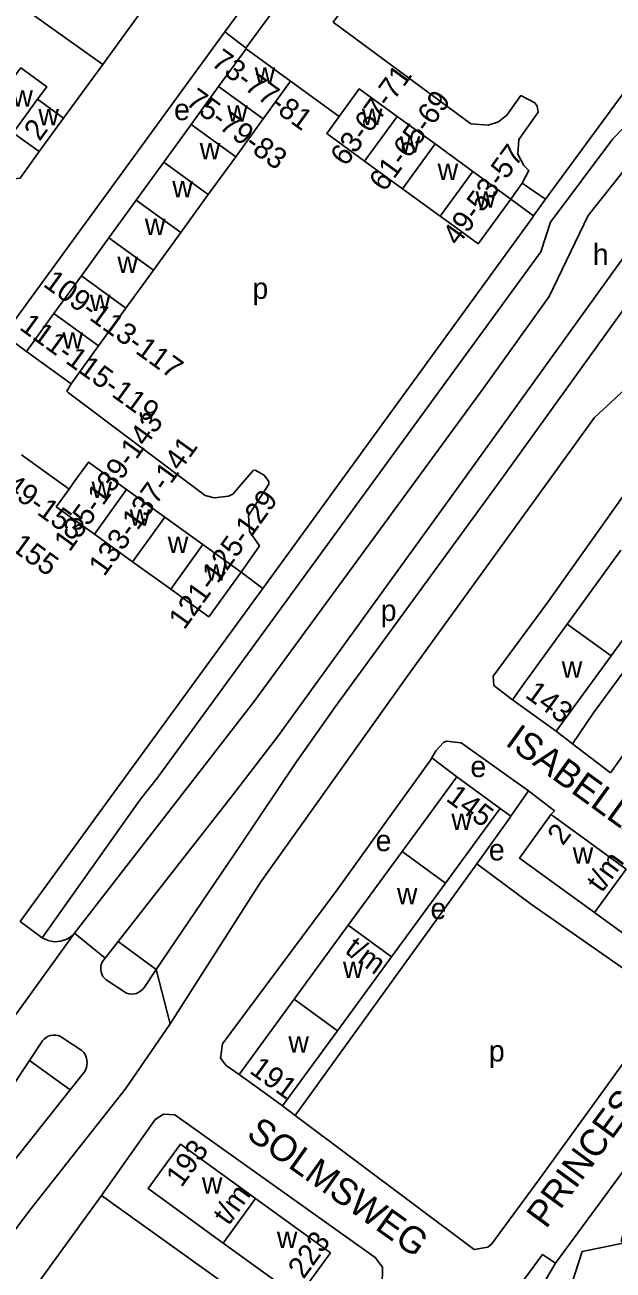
# Model space of a CAD drawing. Extents: x 159700 to 161346, y 381730 to 382922.
# Drawn here: x 160249.2 to 160359.7, y 382348.1 to 382582.1 of the extents above; entities that cross this region are included whole.
import ezdxf

# ---------------------------------------------------------------- set-up
doc = ezdxf.new("R2010")
doc.units = 0
for name, color, linetype in [('BLT_Basislijn', 7, 'Continuous'), ('BLT_Bebouwing', 7, 'Continuous'), ('BLT_Centroide', 7, 'Continuous'), ('BLT_Huisnummer', 7, 'Continuous'), ('BLT_Huisnummer_reeks', 7, 'Continuous'), ('BLT_Onderverdeling_panden', 7, 'Continuous'), ('BLT_Straatnaam', 7, 'Continuous'), ('BLT_Vlakafsluiter', 7, 'Continuous')]:
    doc.layers.add(name, color=color, linetype=linetype)

msp = doc.modelspace()

# ---------------------------------------------------------------- linework, layer by layer
at = {"layer": 'BLT_Basislijn'}
for p, q in [((160271.06, 382584.67), (160263.83, 382574.65)), ((160290.75, 382577.69), (160286.74, 382580.76)), ((160256.43, 382564.58), (160263.83, 382574.65)), ((160308.19, 382564.87), (160299.08, 382571.54)), ((160374.82, 382556.76), (160331.16, 382496.14)), ((160381.75, 382556.63), (160338.62, 382496.66)), ((160342.56, 382552.33), (160340.44, 382549.37)), ((160342.56, 382552.33), (160346.98, 382549.35)), ((160340.44, 382549.37), (160344.73, 382546.2)), ((160346.98, 382549.35), (160344.73, 382546.2)), ((160248.49, 382501.3), (160257.45, 382494.88)), ((160331.16, 382496.14), (160296.61, 382448.35)), ((160289.77, 382479.27), (160293.83, 382476.2)), ((160352.06, 382447.03), (160348.99, 382449.38)), ((160359.21, 382441.57), (160352.06, 382447.03)), ((160325.62, 382444.36), (160330.34, 382440.83)), ((160362.33, 382445.92), (160359.21, 382441.57)), ((160340.46, 382433.42), (160343.76, 382438.15)), ((160340.46, 382433.42), (160338.48, 382434.88)), ((160289.81, 382428.18), (160273.85, 382404.6)), ((160334.1, 382424.48), (160299.96, 382377.17)), ((160252.43, 382410.59), (160248.24, 382413.61)), ((160264.22, 382406.74), (160266.65, 382409.84)), ((160266.65, 382409.84), (160273.85, 382404.6)), ((160273.85, 382404.6), (160271.6, 382401.27)), ((160264.45, 382402.65), (160268.24, 382400.16)), ((160252.21, 382390.8), (160250.04, 382387.54)), ((160256.23, 382391.8), (160259.87, 382389.4)), ((160250.04, 382387.54), (160241.05, 382374.01)), ((160250.04, 382387.54), (160257.68, 382382.01)), ((160260.34, 382385.38), (160257.68, 382382.01)), ((160299.96, 382377.17), (160297.57, 382378.97)), ((160364.74, 382371.06), (160348.85, 382349.46)), ((160222.52, 382305.55), (160263.56, 382362.17)), ((160263.56, 382362.17), (160289.84, 382343.29))]:
    msp.add_line(p, q, dxfattribs=at)
for points in [[(160252.43, 382410.59), (160268.55, 382433.33), (160270.86, 382436.59), (160273.99, 382440.53), (160346.07, 382539.47), (160347.92, 382545.02), (160359.65, 382560.71), (160368.2, 382569.53), (160404.62, 382619.84)], [(160346.98, 382549.35), (160383.64, 382599.24), (160395.79, 382615.95), (160396.1, 382616.35)], [(160425.28, 382599.18), (160384.45, 382546.02), (160383.14, 382544.19), (160379.74, 382536.86), (160366.91, 382518.26), (160360.11, 382511.98), (160356.18, 382508.31), (160321.11, 382459.87)], [(160236.76, 382593.95), (160237.89, 382593.13), (160263.83, 382574.65)], [(160286.74, 382580.76), (160291.43, 382587.22), (160293.69, 382585.93), (160295.34, 382584.47), (160295.34, 382584.08), (160290.68, 382577.74)], [(160342.56, 382552.33), (160343.84, 382554.73), (160342.93, 382555.66), (160341.77, 382557.82), (160341.96, 382560.58), (160345.59, 382565.7), (160345.43, 382566.81), (160344.95, 382567.45), (160342.35, 382568.82), (160339.71, 382565.13), (160338.12, 382563.86), (160336.21, 382563.24), (160332.93, 382563.48), (160307.08, 382582.59), (160308.72, 382584.78)], [(160249.45, 382520.73), (160245.63, 382523.56), (160246.22, 382525.2), (160286.74, 382580.76)], [(160220.9, 382572.04), (160221.91, 382571.31), (160247.19, 382553.19), (160248.27, 382553.3), (160251.85, 382558.28)], [(160335.35, 382513.81), (160347.65, 382531.09), (160354.98, 382546.28), (160365.18, 382559.11), (160370.94, 382564.35)], [(160344.73, 382546.2), (160344.57, 382545.97), (160293.83, 382476.2)], [(160257.83, 382514.65), (160257.05, 382513.28), (160257.35, 382512.93), (160283.05, 382493.69), (160284.74, 382493.23), (160287.44, 382493.52), (160288.2, 382493.94), (160292.05, 382498.39), (160292.43, 382498.44), (160294.12, 382497.47), (160295.01, 382496.31), (160295.01, 382495.77), (160291.16, 382489.9), (160291.35, 382486.93), (160293.23, 382484.24), (160289.77, 382479.27)], [(160376.87, 382515.08), (160376.71, 382514.89), (160347.23, 382473.39), (160337.16, 382459.73), (160337.25, 382457.98), (160340.75, 382455.3)], [(160258.48, 382411.43), (160292.16, 382454.89), (160335.35, 382513.81)], [(160338.62, 382496.66), (160307.61, 382454.24), (160300.02, 382443.37), (160289.81, 382428.18)], [(160352.06, 382447.03), (160355.99, 382452.82), (160386.92, 382495)], [(160293.83, 382476.2), (160293.16, 382475.27), (160262.61, 382433.33), (160248.24, 382413.61)], [(160321.11, 382459.87), (160293.47, 382421.11), (160276.46, 382394.4)], [(160266.65, 382409.84), (160288.26, 382437.48), (160296.61, 382448.35)], [(160325.62, 382444.36), (160326.38, 382445.67), (160327.78, 382447.24), (160328.35, 382447.51), (160331.13, 382447.19), (160343.76, 382438.15)], [(160325.62, 382444.36), (160325.39, 382443.97), (160317.72, 382433.33), (160307.8, 382419.59), (160287.91, 382392.83), (160286.3, 382390.66), (160285.88, 382387.95), (160286.99, 382386.58), (160289.43, 382384.9)], [(160347.99, 382433.72), (160348.68, 382434.43), (160343.76, 382438.15)], [(160340.46, 382433.42), (160340.4, 382433.33), (160340.26, 382433.13), (160334.1, 382424.48)], [(160370.12, 382398.86), (160344.36, 382416.84), (160334.1, 382424.48)], [(160252.43, 382410.59), (160252.96, 382410.29), (160253.52, 382410.06), (160254.1, 382409.91), (160254.7, 382409.83), (160255.31, 382409.84), (160255.91, 382409.92), (160256.49, 382410.09), (160257.05, 382410.32), (160257.57, 382410.63), (160258.05, 382411.01), (160258.48, 382411.43)], [(160264.22, 382406.74), (160263.92, 382406.39), (160263.68, 382405.99), (160263.51, 382405.56), (160263.42, 382405.1), (160263.4, 382404.64), (160263.47, 382404.17), (160263.62, 382403.73), (160263.83, 382403.32), (160264.12, 382402.95), (160264.45, 382402.65)], [(160268.24, 382400.16), (160268.7, 382400.04), (160269.18, 382399.99), (160269.65, 382400.02), (160270.12, 382400.13), (160270.55, 382400.32), (160270.96, 382400.58), (160271.31, 382400.9), (160271.6, 382401.27)], [(160370.12, 382398.86), (160345.89, 382365.34), (160336.84, 382353), (160336.12, 382352.42), (160333.57, 382352.01), (160299.96, 382377.17)], [(160252.21, 382390.8), (160252.45, 382391.19), (160252.77, 382391.54), (160253.14, 382391.84), (160253.55, 382392.06), (160253.99, 382392.21), (160254.46, 382392.29), (160254.93, 382392.28), (160255.39, 382392.2), (160255.83, 382392.04), (160256.23, 382391.8)], [(160259.87, 382389.4), (160260.21, 382389.03), (160260.48, 382388.61), (160260.68, 382388.15), (160260.81, 382387.66), (160260.86, 382387.16), (160260.82, 382386.66), (160260.71, 382386.17), (160260.52, 382385.7), (160260.34, 382385.38)], [(160268.06, 382382.16), (160250.09, 382359.39), (160227.78, 382329.64), (160218.64, 382317.56)], [(160257.68, 382382.01), (160245.47, 382366.57), (160235.17, 382353.39)], [(160263.56, 382362.17), (160273.65, 382376.41), (160275.21, 382377.4), (160277.31, 382377.32), (160314.98, 382350.52), (160316.33, 382348.65), (160316.27, 382345.15), (160306.26, 382331.32)], [(160348.85, 382349.46), (160346.41, 382351.06), (160336.64, 382337.81)], [(160348.85, 382349.46), (160346.62, 382345.61), (160348.72, 382343.73)]]:
    msp.add_lwpolyline(points, dxfattribs=at)
at = {"layer": 'BLT_Bebouwing'}
for p, q in [((160290.7, 382577.62), (160285.55, 382570.51)), ((160290.75, 382577.69), (160290.7, 382577.62)), ((160299.08, 382571.54), (160290.7, 382577.62)), ((160293.93, 382564.43), (160299.08, 382571.54)), ((160285.55, 382570.51), (160280.39, 382563.4)), ((160251.54, 382568.13), (160256.43, 382564.58)), ((160256.43, 382564.58), (160251.85, 382558.28)), ((160288.77, 382557.32), (160293.93, 382564.43)), ((160326.21, 382559.72), (160319.09, 382564.9)), ((160251.85, 382558.28), (160246.96, 382561.83)), ((160280.39, 382563.4), (160275.23, 382556.29)), ((160333.32, 382554.55), (160326.21, 382559.72)), ((160283.62, 382550.21), (160288.77, 382557.32)), ((160275.23, 382556.29), (160270.08, 382549.18)), ((160320.1, 382551.32), (160312.98, 382556.5)), ((160340.44, 382549.37), (160333.32, 382554.55)), ((160278.46, 382543.1), (160283.62, 382550.21)), ((160327.21, 382546.15), (160320.1, 382551.32)), ((160270.08, 382549.18), (160264.92, 382542.06)), ((160273.3, 382535.98), (160278.46, 382543.1)), ((160264.92, 382542.06), (160259.76, 382534.95)), ((160268.15, 382528.87), (160273.3, 382535.98)), ((160259.76, 382534.95), (160254.61, 382527.84)), ((160262.99, 382521.76), (160268.15, 382528.87)), ((160254.61, 382527.84), (160249.45, 382520.73)), ((160257.83, 382514.65), (160262.99, 382521.76)), ((160249.45, 382520.73), (160257.83, 382514.65)), ((160268.27, 382494.78), (160275.44, 382489.61)), ((160275.44, 382489.61), (160282.6, 382484.44)), ((160269.39, 382481.23), (160262.22, 382486.4)), ((160282.6, 382484.44), (160289.77, 382479.27)), ((160351.05, 382469.51), (160361.13, 382483.42)), ((160276.55, 382476.06), (160269.39, 382481.23)), ((160369.38, 382477.42), (160359.28, 382463.53)), ((160342.93, 382458.29), (160351.05, 382469.51)), ((160359.28, 382463.53), (160348.99, 382449.38)), ((160340.75, 382455.3), (160342.93, 382458.29)), ((160348.99, 382449.38), (160340.75, 382455.3)), ((160330.34, 382440.83), (160338.48, 382434.88)), ((160309.91, 382412.91), (160320.07, 382426.8)), ((160328.21, 382420.84), (160318.05, 382406.96)), ((160299.76, 382399.03), (160309.91, 382412.91)), ((160318.05, 382406.96), (160307.89, 382393.08)), ((160289.43, 382384.9), (160299.76, 382399.03)), ((160307.89, 382393.08), (160297.57, 382378.97))]:
    msp.add_line(p, q, dxfattribs=at)
for points in [[(160246.65, 382571.69), (160248.37, 382574.02), (160253.25, 382570.48), (160251.54, 382568.13)], [(160308.19, 382564.87), (160309.03, 382566.03), (160311.97, 382570.07), (160319.09, 382564.9)], [(160312.98, 382556.5), (160305.86, 382561.67), (160308.19, 382564.87)], [(160340.44, 382549.37), (160334.33, 382540.97), (160330.29, 382543.91), (160327.21, 382546.15)], [(160257.45, 382494.88), (160258.24, 382495.97), (160261.11, 382499.95), (160268.27, 382494.78)], [(160262.22, 382486.4), (160255.06, 382491.57), (160257.45, 382494.88)], [(160289.77, 382479.27), (160283.72, 382470.89), (160279.66, 382473.81), (160276.55, 382476.06)], [(160320.07, 382426.8), (160324.85, 382433.33), (160330.34, 382440.83)], [(160338.48, 382434.88), (160337.35, 382433.33), (160328.21, 382420.84)], [(160356.19, 382415.29), (160342.06, 382425.54), (160347.71, 382433.33), (160347.99, 382433.72)], [(160347.99, 382433.72), (160348.52, 382433.33), (160362.12, 382423.47)], [(160376.16, 382413.28), (160370.23, 382405.1), (160356.19, 382415.29)], [(160297.57, 382378.97), (160295.21, 382380.69), (160289.43, 382384.9)], [(160292.47, 382361.56), (160278.39, 382371.77), (160274.96, 382367.09), (160272.32, 382363.44), (160286.43, 382353.22)], [(160377.35, 382363.46), (160370.02, 382365.33), (160363.3, 382361.3), (160361.16, 382353.54), (160361.54, 382353.21), (160353.83, 382351.61)], [(160286.43, 382353.22), (160300.54, 382343), (160302.22, 382345.33), (160306.56, 382351.36), (160292.47, 382361.56)], [(160351.21, 382343.48), (160353.83, 382351.61)]]:
    msp.add_lwpolyline(points, dxfattribs=at)
at = {"layer": 'BLT_Onderverdeling_panden'}
for p, q in [((160293.93, 382564.43), (160285.55, 382570.51)), ((160246.96, 382561.83), (160251.54, 382568.13)), ((160312.98, 382556.5), (160319.09, 382564.9)), ((160288.77, 382557.32), (160280.39, 382563.4)), ((160320.1, 382551.32), (160326.21, 382559.72)), ((160283.62, 382550.21), (160275.23, 382556.29)), ((160327.21, 382546.15), (160333.32, 382554.55)), ((160278.46, 382543.1), (160270.08, 382549.18)), ((160273.3, 382535.98), (160264.92, 382542.06)), ((160268.15, 382528.87), (160259.76, 382534.95)), ((160262.99, 382521.76), (160254.61, 382527.84)), ((160262.22, 382486.4), (160268.27, 382494.78)), ((160269.39, 382481.23), (160275.44, 382489.61)), ((160276.55, 382476.06), (160282.6, 382484.44)), ((160351.05, 382469.51), (160359.28, 382463.53)), ((160320.07, 382426.8), (160328.21, 382420.84)), ((160362.12, 382423.47), (160356.19, 382415.29)), ((160309.91, 382412.91), (160318.05, 382406.96)), ((160299.76, 382399.03), (160307.89, 382393.08)), ((160292.47, 382361.56), (160286.43, 382353.22))]:
    msp.add_line(p, q, dxfattribs=at)
at = {"layer": 'BLT_Vlakafsluiter'}
for p, q in [((160258.48, 382411.43), (160246.12, 382394.33)), ((160264.22, 382406.74), (160258.48, 382411.43)), ((160273.85, 382404.6), (160276.46, 382394.4)), ((160276.46, 382394.4), (160268.06, 382382.16))]:
    msp.add_line(p, q, dxfattribs=at)

# ---------------------------------------------------------------- texts
at = {"layer": 'BLT_Centroide'}
for s, p in [('w', (160292.32, 382571.03)), ('w', (160246.8, 382566.75)), ('w', (160251.69, 382563.2)), ('e', (160277.18, 382564.2)), ('w', (160287.16, 382563.91)), ('w', (160312.47, 382563.3)), ('w', (160282.01, 382556.81)), ('w', (160319.59, 382558.11)), ('w', (160326.7, 382552.92)), ('w', (160276.85, 382549.69)), ('w', (160333.83, 382547.77)), ('w', (160271.7, 382542.59)), ('h', (160355.85, 382536.98)), ('w', (160266.54, 382535.47)), ('p', (160291.91, 382530.61)), ('w', (160261.38, 382528.34)), ('w', (160256.22, 382521.25)), ('w', (160261.67, 382493.19)), ('w', (160268.83, 382488)), ('w', (160276, 382482.84)), ('w', (160283.16, 382477.66)), ('p', (160316.01, 382470.1)), ('w', (160350.02, 382459.42)), ('e', (160332.86, 382440.75)), ('w', (160329.28, 382430.84)), ('e', (160315.05, 382426.85)), ('e', (160336.33, 382425.11)), ('w', (160352.09, 382424.5)), ('w', (160319.06, 382416.88)), ('e', (160325.37, 382414.06)), ('w', (160308.91, 382403)), ('w', (160298.66, 382389)), ('p', (160336.33, 382387.32)), ('w', (160282.41, 382362.5)), ('w', (160296.5, 382352.28))]:
    msp.add_text(s, height=4, dxfattribs=at).set_placement(p)
at = {"layer": 'BLT_Huisnummer'}
msp.add_text('2', height=4, rotation=53.9688, dxfattribs=at).set_placement((160251.91, 382560.09))
at = {"layer": 'BLT_Huisnummer_reeks'}
for s, rotation, p in [('73-77-81', 324.054, (160283.95, 382574.62)), ('63-67-71', 53.9718, (160309.46, 382555.34)), ('75-79-83', 324.054, (160279.17, 382567.25)), ('61-65-69', 53.9718, (160316.74, 382550.57)), ('49-53-57', 53.9674, (160330.53, 382540.4)), ('109-113-117', 324.054, (160252.4, 382533.12)), ('111-115-119', 324.0584, (160247.93, 382525)), ('135-139-143', 54.1866, (160257.55, 382482.91)), ('145-149-153', 324.0477, (160233.9, 382502.84)), ('133-137-141', 54.1866, (160264.05, 382478.29)), ('147-151-155', 324.0465, (160229, 382496.15)), ('121-125-129', 54.1853, (160279.1, 382468.28)), ('143', 323.9921, (160342.94, 382455.9)), ('145', 323.7935, (160328.08, 382436.44)), ('2', 54.0431, (160350.25, 382427.72)), ('t/m', 54.0318, (160357.58, 382418.89)), ('t/m', 323.8049, (160309.06, 382407.86)), ('191', 323.9296, (160291.16, 382385.31)), ('193', 53.7891, (160278.56, 382363.5)), ('t/m', 54.2874, (160287.43, 382356.34)), ('223', 54.2874, (160301.51, 382346.29))]:
    msp.add_text(s, height=4, rotation=rotation, dxfattribs=at).set_placement(p)
at = {"layer": 'BLT_Straatnaam'}
for s, rotation, p in [('ISABELLASTRAAT', 324.0317, (160339.21, 382446.94)), ('PRINCESSENLAAN', 53.6642, (160347.08, 382355.73)), ('SOLMSWEG', 324.572, (160290.54, 382373.16))]:
    msp.add_text(s, height=5, rotation=rotation, dxfattribs=at).set_placement(p)

doc.saveas('drawing.dxf')
